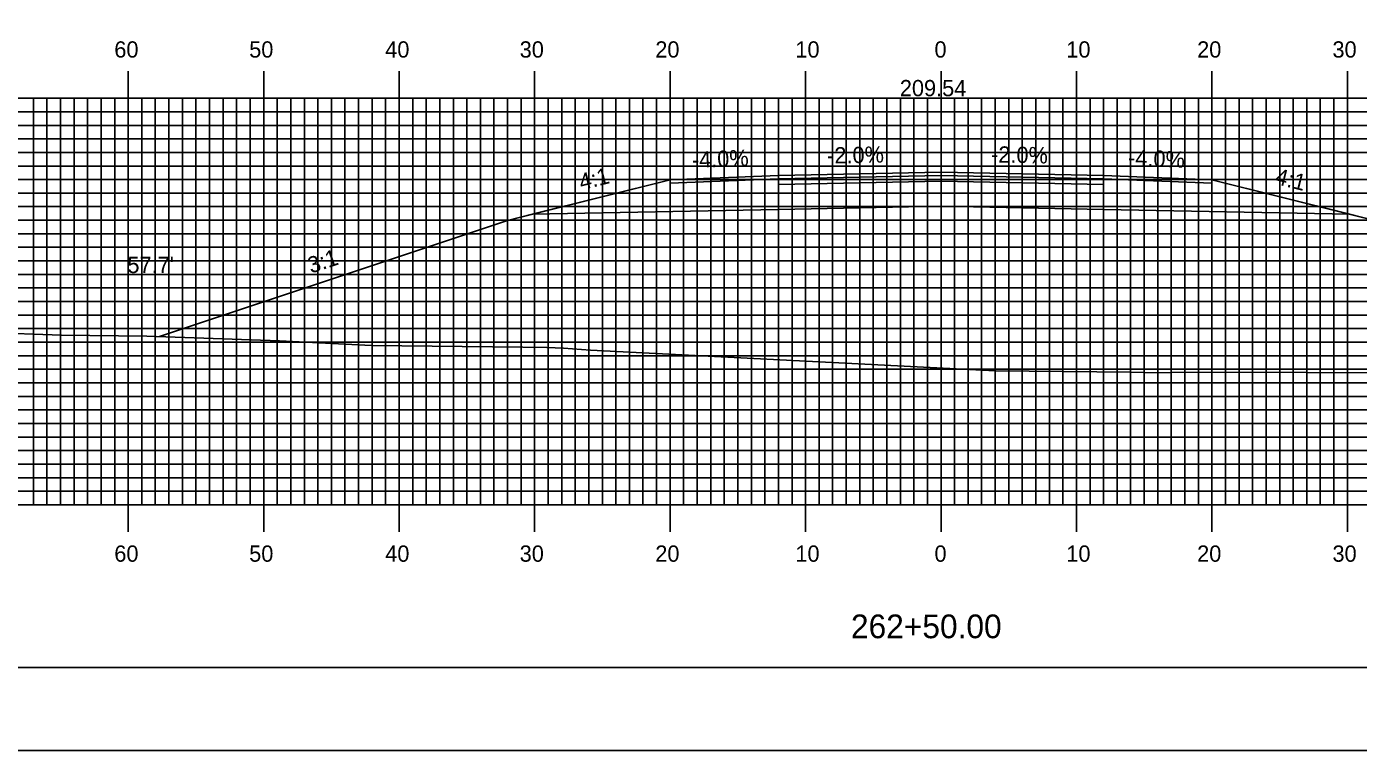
# Model space of a CAD drawing. Extents: x 1806651 to 1806995, y 442591 to 442811.
# Drawn here: x 1806749.7 to 1806848.1, y 442590.5 to 442643.9 of the extents above; entities that cross this region are included whole.
import ezdxf

# ---------------------------------------------------------------- set-up
doc = ezdxf.new("R2010")
doc.units = 0
for name, color, linetype in [('ANNOTATION', 7, 'Continuous'), ('BORDER', 7, 'Continuous'), ('D_Roadway_Centerline', 7, 'Continuous'), ('D_Roadway_Centerline_Text', 7, 'Continuous'), ('D_Roadway_Edge_Shoulder', 7, 'Continuous'), ('D_Roadway_Edge_TW', 7, 'Continuous'), ('D_Roadway_Pavement', 7, 'Continuous'), ('D_Roadway_SlopeLines', 7, 'Continuous'), ('D_Roadway_SubGrade', 7, 'Continuous'), ('D_Text_Standard', 7, 'Continuous'), ('H_V ANNOTATION', 7, 'Continuous'), ('MAJOR', 7, 'Continuous'), ('MINOR', 7, 'Continuous'), ('PLOT BOUNDARY', 7, 'Continuous'), ('S_Roadway_Centerline', 7, 'Continuous')]:
    doc.layers.add(name, color=color, linetype=linetype)

msp = doc.modelspace()

# ---------------------------------------------------------------- linework, layer by layer
at = {"layer": 'BORDER'}
msp.add_lwpolyline([(1806667.646, 442596.665), (1806987.646, 442596.665), (1806987.646, 442806.665), (1806667.646, 442806.665)], close=True, dxfattribs=at)
at = {"layer": 'D_Roadway_Centerline'}
msp.add_lwpolyline([(1806759.555, 442621.083), (1806785.246, 442629.646), (1806787.072, 442630.103), (1806797.246, 442632.646), (1806805.246, 442632.966), (1806817.246, 442633.206), (1806829.246, 442632.966), (1806837.246, 442632.646), (1806847.42, 442630.103), (1806849.246, 442629.646), (1806885.008, 442617.726)], dxfattribs=at)
at = {"layer": 'D_Roadway_Edge_Shoulder'}
for points in [[(1806805.246, 442632.966), (1806797.246, 442632.646), (1806797.246, 442632.396), (1806805.246, 442632.716)], [(1806829.246, 442632.966), (1806837.246, 442632.646), (1806837.246, 442632.396), (1806829.246, 442632.716)]]:
    msp.add_lwpolyline(points, close=True, dxfattribs=at)
at = {"layer": 'D_Roadway_Edge_TW'}
msp.add_lwpolyline([(1806805.246, 442632.716), (1806805.246, 442632.966), (1806817.246, 442633.206), (1806829.246, 442632.966), (1806829.246, 442632.716), (1806817.246, 442632.956)], close=True, dxfattribs=at)
at = {"layer": 'D_Roadway_Pavement'}
msp.add_lwpolyline([(1806805.246, 442632.3), (1806805.246, 442632.716), (1806817.246, 442632.956), (1806829.246, 442632.716), (1806829.246, 442632.3), (1806817.246, 442632.54)], close=True, dxfattribs=at)
at = {"layer": 'D_Roadway_SlopeLines'}
for points in [[(1806797.246, 442632.646), (1806785.246, 442629.646), (1806759.555, 442621.083)], [(1806837.246, 442632.646), (1806849.246, 442629.646), (1806885.008, 442617.726)]]:
    msp.add_lwpolyline(points, dxfattribs=at)
at = {"layer": 'D_Roadway_SubGrade'}
msp.add_lwpolyline([(1806805.246, 442630.466), (1806787.072, 442630.103), (1806797.246, 442632.646), (1806797.246, 442632.396), (1806805.246, 442632.716), (1806817.246, 442632.956), (1806829.246, 442632.716), (1806837.246, 442632.396), (1806837.246, 442632.646), (1806847.42, 442630.103), (1806829.246, 442630.466), (1806817.246, 442630.706)], close=True, dxfattribs=at)
at = {"layer": 'MAJOR'}
for p, q in [((1806757.246, 442640.669), (1806757.246, 442638.665)), ((1806767.246, 442640.669), (1806767.246, 442638.665)), ((1806777.246, 442640.669), (1806777.246, 442638.665)), ((1806787.246, 442640.669), (1806787.246, 442638.665)), ((1806797.246, 442640.669), (1806797.246, 442638.665)), ((1806807.246, 442640.669), (1806807.246, 442638.665)), ((1806817.246, 442640.669), (1806817.246, 442638.665)), ((1806827.246, 442640.669), (1806827.246, 442638.665)), ((1806837.246, 442640.669), (1806837.246, 442638.665)), ((1806847.246, 442640.669), (1806847.246, 442638.665)), ((1806677.246, 442638.665), (1806957.246, 442638.665)), ((1806677.246, 442638.665), (1806957.246, 442638.665)), ((1806757.246, 442608.665), (1806757.246, 442638.665)), ((1806767.246, 442608.665), (1806767.246, 442638.665)), ((1806777.246, 442608.665), (1806777.246, 442638.665)), ((1806787.246, 442608.665), (1806787.246, 442638.665)), ((1806797.246, 442608.665), (1806797.246, 442638.665)), ((1806807.246, 442608.665), (1806807.246, 442638.665)), ((1806817.246, 442608.665), (1806817.246, 442638.665)), ((1806827.246, 442608.665), (1806827.246, 442638.665)), ((1806837.246, 442608.665), (1806837.246, 442638.665)), ((1806847.246, 442608.665), (1806847.246, 442638.665)), ((1806677.246, 442633.665), (1806957.246, 442633.665)), ((1806677.246, 442628.665), (1806957.246, 442628.665)), ((1806677.246, 442623.665), (1806957.246, 442623.665)), ((1806677.246, 442618.665), (1806957.246, 442618.665)), ((1806677.246, 442613.665), (1806957.246, 442613.665)), ((1806677.246, 442608.665), (1806957.246, 442608.665)), ((1806677.246, 442608.665), (1806957.246, 442608.665)), ((1806757.246, 442606.661), (1806757.246, 442608.665)), ((1806767.246, 442606.661), (1806767.246, 442608.665)), ((1806777.246, 442606.661), (1806777.246, 442608.665)), ((1806787.246, 442606.661), (1806787.246, 442608.665)), ((1806797.246, 442606.661), (1806797.246, 442608.665)), ((1806807.246, 442606.661), (1806807.246, 442608.665)), ((1806817.246, 442606.661), (1806817.246, 442608.665)), ((1806827.246, 442606.661), (1806827.246, 442608.665)), ((1806837.246, 442606.661), (1806837.246, 442608.665)), ((1806847.246, 442606.661), (1806847.246, 442608.665))]:
    msp.add_line(p, q, dxfattribs=at)
at = {"layer": 'MINOR'}
for p, q in [((1806750.246, 442608.665), (1806750.246, 442638.665)), ((1806751.246, 442608.665), (1806751.246, 442638.665)), ((1806752.246, 442608.665), (1806752.246, 442638.665)), ((1806753.246, 442608.665), (1806753.246, 442638.665)), ((1806754.246, 442608.665), (1806754.246, 442638.665)), ((1806755.246, 442608.665), (1806755.246, 442638.665)), ((1806756.246, 442608.665), (1806756.246, 442638.665)), ((1806758.246, 442608.665), (1806758.246, 442638.665)), ((1806759.246, 442608.665), (1806759.246, 442638.665)), ((1806760.246, 442608.665), (1806760.246, 442638.665)), ((1806761.246, 442608.665), (1806761.246, 442638.665)), ((1806762.246, 442608.665), (1806762.246, 442638.665)), ((1806763.246, 442608.665), (1806763.246, 442638.665)), ((1806764.246, 442608.665), (1806764.246, 442638.665)), ((1806765.246, 442608.665), (1806765.246, 442638.665)), ((1806766.246, 442608.665), (1806766.246, 442638.665)), ((1806768.246, 442608.665), (1806768.246, 442638.665)), ((1806769.246, 442608.665), (1806769.246, 442638.665)), ((1806770.246, 442608.665), (1806770.246, 442638.665)), ((1806771.246, 442608.665), (1806771.246, 442638.665)), ((1806772.246, 442608.665), (1806772.246, 442638.665)), ((1806773.246, 442608.665), (1806773.246, 442638.665)), ((1806774.246, 442608.665), (1806774.246, 442638.665)), ((1806775.246, 442608.665), (1806775.246, 442638.665)), ((1806776.246, 442608.665), (1806776.246, 442638.665)), ((1806778.246, 442608.665), (1806778.246, 442638.665)), ((1806779.246, 442608.665), (1806779.246, 442638.665)), ((1806780.246, 442608.665), (1806780.246, 442638.665)), ((1806781.246, 442608.665), (1806781.246, 442638.665)), ((1806782.246, 442608.665), (1806782.246, 442638.665)), ((1806783.246, 442608.665), (1806783.246, 442638.665)), ((1806784.246, 442608.665), (1806784.246, 442638.665)), ((1806785.246, 442608.665), (1806785.246, 442638.665)), ((1806786.246, 442608.665), (1806786.246, 442638.665)), ((1806788.246, 442608.665), (1806788.246, 442638.665)), ((1806789.246, 442608.665), (1806789.246, 442638.665)), ((1806790.246, 442608.665), (1806790.246, 442638.665)), ((1806791.246, 442608.665), (1806791.246, 442638.665)), ((1806792.246, 442608.665), (1806792.246, 442638.665)), ((1806793.246, 442608.665), (1806793.246, 442638.665)), ((1806794.246, 442608.665), (1806794.246, 442638.665)), ((1806795.246, 442608.665), (1806795.246, 442638.665)), ((1806796.246, 442608.665), (1806796.246, 442638.665)), ((1806798.246, 442608.665), (1806798.246, 442638.665)), ((1806799.246, 442608.665), (1806799.246, 442638.665)), ((1806800.246, 442608.665), (1806800.246, 442638.665)), ((1806801.246, 442608.665), (1806801.246, 442638.665)), ((1806802.246, 442608.665), (1806802.246, 442638.665)), ((1806803.246, 442608.665), (1806803.246, 442638.665)), ((1806804.246, 442608.665), (1806804.246, 442638.665)), ((1806805.246, 442608.665), (1806805.246, 442638.665)), ((1806806.246, 442608.665), (1806806.246, 442638.665)), ((1806808.246, 442608.665), (1806808.246, 442638.665)), ((1806809.246, 442608.665), (1806809.246, 442638.665)), ((1806810.246, 442608.665), (1806810.246, 442638.665)), ((1806811.246, 442608.665), (1806811.246, 442638.665)), ((1806812.246, 442608.665), (1806812.246, 442638.665)), ((1806813.246, 442608.665), (1806813.246, 442638.665)), ((1806814.246, 442608.665), (1806814.246, 442638.665)), ((1806815.246, 442608.665), (1806815.246, 442638.665)), ((1806816.246, 442608.665), (1806816.246, 442638.665)), ((1806818.246, 442608.665), (1806818.246, 442638.665)), ((1806819.246, 442608.665), (1806819.246, 442638.665)), ((1806820.246, 442608.665), (1806820.246, 442638.665)), ((1806821.246, 442608.665), (1806821.246, 442638.665)), ((1806822.246, 442608.665), (1806822.246, 442638.665)), ((1806823.246, 442608.665), (1806823.246, 442638.665)), ((1806824.246, 442608.665), (1806824.246, 442638.665)), ((1806825.246, 442608.665), (1806825.246, 442638.665)), ((1806826.246, 442608.665), (1806826.246, 442638.665)), ((1806828.246, 442608.665), (1806828.246, 442638.665)), ((1806829.246, 442608.665), (1806829.246, 442638.665)), ((1806830.246, 442608.665), (1806830.246, 442638.665)), ((1806831.246, 442608.665), (1806831.246, 442638.665)), ((1806832.246, 442608.665), (1806832.246, 442638.665)), ((1806833.246, 442608.665), (1806833.246, 442638.665)), ((1806834.246, 442608.665), (1806834.246, 442638.665)), ((1806835.246, 442608.665), (1806835.246, 442638.665)), ((1806836.246, 442608.665), (1806836.246, 442638.665)), ((1806838.246, 442608.665), (1806838.246, 442638.665)), ((1806839.246, 442608.665), (1806839.246, 442638.665)), ((1806840.246, 442608.665), (1806840.246, 442638.665)), ((1806841.246, 442608.665), (1806841.246, 442638.665)), ((1806842.246, 442608.665), (1806842.246, 442638.665)), ((1806843.246, 442608.665), (1806843.246, 442638.665)), ((1806844.246, 442608.665), (1806844.246, 442638.665)), ((1806845.246, 442608.665), (1806845.246, 442638.665)), ((1806846.246, 442608.665), (1806846.246, 442638.665)), ((1806677.246, 442637.665), (1806957.246, 442637.665)), ((1806677.246, 442636.665), (1806957.246, 442636.665)), ((1806677.246, 442635.665), (1806957.246, 442635.665)), ((1806677.246, 442634.665), (1806957.246, 442634.665)), ((1806677.246, 442632.665), (1806957.246, 442632.665)), ((1806677.246, 442631.665), (1806957.246, 442631.665)), ((1806677.246, 442630.665), (1806957.246, 442630.665)), ((1806677.246, 442629.665), (1806957.246, 442629.665)), ((1806677.246, 442627.665), (1806957.246, 442627.665)), ((1806677.246, 442626.665), (1806957.246, 442626.665)), ((1806677.246, 442625.665), (1806957.246, 442625.665)), ((1806677.246, 442624.665), (1806957.246, 442624.665)), ((1806677.246, 442622.665), (1806957.246, 442622.665)), ((1806677.246, 442621.665), (1806957.246, 442621.665)), ((1806677.246, 442620.665), (1806957.246, 442620.665)), ((1806677.246, 442619.665), (1806957.246, 442619.665)), ((1806677.246, 442617.665), (1806957.246, 442617.665)), ((1806677.246, 442616.665), (1806957.246, 442616.665)), ((1806677.246, 442615.665), (1806957.246, 442615.665)), ((1806677.246, 442614.665), (1806957.246, 442614.665)), ((1806677.246, 442612.665), (1806957.246, 442612.665)), ((1806677.246, 442611.665), (1806957.246, 442611.665)), ((1806677.246, 442610.665), (1806957.246, 442610.665)), ((1806677.246, 442609.665), (1806957.246, 442609.665))]:
    msp.add_line(p, q, dxfattribs=at)
at = {"layer": 'PLOT BOUNDARY'}
msp.add_lwpolyline([(1806651.459, 442590.547), (1806991.459, 442590.547), (1806991.459, 442810.547), (1806651.459, 442810.547)], close=True, dxfattribs=at)
at = {"layer": 'S_Roadway_Centerline'}
msp.add_lwpolyline([(1806677.246, 442624.403), (1806681.745, 442624.346), (1806703.745, 442623.321), (1806707.773, 442623.066), (1806716.711, 442622.687), (1806724.729, 442621.954), (1806741.002, 442621.601), (1806746.811, 442621.387), (1806752.325, 442621.195), (1806758.609, 442621.116), (1806768.42, 442620.771), (1806775.205, 442620.419), (1806786.382, 442620.301), (1806788.136, 442620.271), (1806789.367, 442620.213), (1806791.37, 442620.082), (1806821.277, 442618.559), (1806831.227, 442618.464), (1806833.218, 442618.413), (1806835.259, 442618.455), (1806853.243, 442618.411)], dxfattribs=at)

# ---------------------------------------------------------------- texts
at = {"layer": 'ANNOTATION'}
for s, rotation, p in [('-2.0%', 1.14576, (1806808.852, 442633.839)), ('-2.0%', 358.85424, (1806820.932, 442633.933)), ('-4.0%', 2.29061, (1806798.878, 442633.513)), ('-4.0%', 357.70939, (1806831.037, 442633.696)), ('4:1', 14.03624, (1806790.694, 442631.87)), ('4:1', 345.96376, (1806841.838, 442632.36)), ('3:1', 18.43478, (1806770.739, 442625.719))]:
    msp.add_text(s, height=1.2, rotation=rotation, dxfattribs=at).set_placement(p)
at = {"layer": 'D_Roadway_Centerline'}
for s, p in [('C', (1806817.24, 442633.206)), ('L', (1806817.246, 442633.199))]:
    msp.add_text(s, height=0.0146, dxfattribs=at).set_placement(p)
at = {"layer": 'D_Roadway_Centerline_Text'}
msp.add_text('209.54', height=1.2, dxfattribs=at).set_placement((1806814.206, 442638.813))
at = {"layer": 'D_Text_Standard'}
msp.add_text("57.7'", height=1.2, dxfattribs=at).set_placement((1806757.185, 442625.764))
at = {"layer": 'H_V ANNOTATION'}
for s, height, p in [('60', 1.2, (1806756.218, 442641.665)), ('50', 1.2, (1806766.175, 442641.665)), ('40', 1.2, (1806776.218, 442641.665)), ('30', 1.2, (1806786.143, 442641.665)), ('20', 1.2, (1806796.154, 442641.665)), ('10', 1.2, (1806806.496, 442641.665)), ('0', 1.2, (1806816.764, 442641.665)), ('10', 1.2, (1806826.496, 442641.665)), ('20', 1.2, (1806836.154, 442641.665)), ('30', 1.2, (1806846.143, 442641.665)), ('60', 1.2, (1806756.218, 442604.465)), ('50', 1.2, (1806766.175, 442604.465)), ('40', 1.2, (1806776.218, 442604.465)), ('30', 1.2, (1806786.143, 442604.465)), ('20', 1.2, (1806796.154, 442604.465)), ('10', 1.2, (1806806.496, 442604.465)), ('0', 1.2, (1806816.764, 442604.465)), ('10', 1.2, (1806826.496, 442604.465)), ('20', 1.2, (1806836.154, 442604.465)), ('30', 1.2, (1806846.143, 442604.465)), ('262+50.00', 1.75, (1806810.597, 442598.821))]:
    msp.add_text(s, height=height, dxfattribs=at).set_placement(p)

doc.saveas('drawing.dxf')
